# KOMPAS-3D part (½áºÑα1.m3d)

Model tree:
1. Эскиз:1
2. Операция выдавливания:1
     Расстояние 1 = 8.7
3. Эскиз:2
4. Операция выдавливания:2
     Расстояние 1 = 0.5
5. Эскиз:3
6. Операция выдавливания:3
     Расстояние 1 = 0.5
7. Эскиз:4
8. Операция выдавливания:5
     Расстояние 1 = 4; Угол 1 = 6
9. Эскиз:5
10. Операция выдавливания:6
     Расстояние 1 = 0.5
11. Эскиз:6
12. Операция выдавливания:7
     Расстояние 1 = 0.5
13. Эскиз:8
14. Операция выдавливания:8
     Расстояние 1 = 2; Расстояние 2 = 5
15. Эскиз:9
16. Операция выдавливания:9
     Расстояние 1 = 0.1; Расстояние 2 = 3
17. Эскиз:11
18. Операция выдавливания:10
     Расстояние 1 = 0.3; Расстояние 2 = 1.5
19. Скругление:10
     Радиус = 0.5
20. Эскиз:12
21. Операция выдавливания:11
     Расстояние 1 = 0.3; Расстояние 2 = 0.8
22. Эскиз:13
23. Вырезать элемент выдавливания:1
     Расстояние 1 = 0.1
24. Эскиз:14
25. Операция выдавливания:12
     Расстояние 1 = 0.3; Расстояние 2 = 0.8
26. Эскиз:15
27. Операция выдавливания:13
     Расстояние 1 = 0.3; Расстояние 2 = 0.8
28. Эскиз:16
29. Операция выдавливания:14
     Расстояние 1 = 0.3; Расстояние 2 = 0.8
30. Зеркальный массив:2  (with: Операция выдавливания:1, Операция выдавливания:2, Операция выдавливания:3, Операция выдавливания:5, Операция выдавливания:6, Операция выдавливания:7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)  (labels: Экземпляр ( 1 ); Экземпляр ( 2 ))
31. Эскиз:17
32. Операция выдавливания:15
     Расстояние 1 = 0.3; Расстояние 2 = 0.8
33. Скругление:16
     Радиус = 0.1
34. Скругление:17
     Радиус = 1
35. Скругление:18
     Радиус = 0.5
36. Скругление:19
     Радиус = 0.5
37. Скругление:20
     Радиус = 0.1
38. Скругление:21
     Радиус = 0.1
39. Массив по концентрической сетке:2  (with: Операция выдавливания:12)  (labels: Экземпляр ( 1, 1 ); Экземпляр ( 1, 2 ); Экземпляр ( 1, 3 ); Экземпляр ( 1, 4 ))
     N 2 = 4; Шаг 2 = 360; Номер 2 = 1
40. Эскиз:18
41. Операция выдавливания:16
     Расстояние 1 = 0.3; Расстояние 2 = 0.8
42. Скругление:23
     Радиус = 0.2
43. Скругление:24
     Радиус = 0.5

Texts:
  лазер1
  Сплав АЛ8  ГОСТ 1583-93
  Экземпляр ( 1 )
  Экземпляр ( 2 )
